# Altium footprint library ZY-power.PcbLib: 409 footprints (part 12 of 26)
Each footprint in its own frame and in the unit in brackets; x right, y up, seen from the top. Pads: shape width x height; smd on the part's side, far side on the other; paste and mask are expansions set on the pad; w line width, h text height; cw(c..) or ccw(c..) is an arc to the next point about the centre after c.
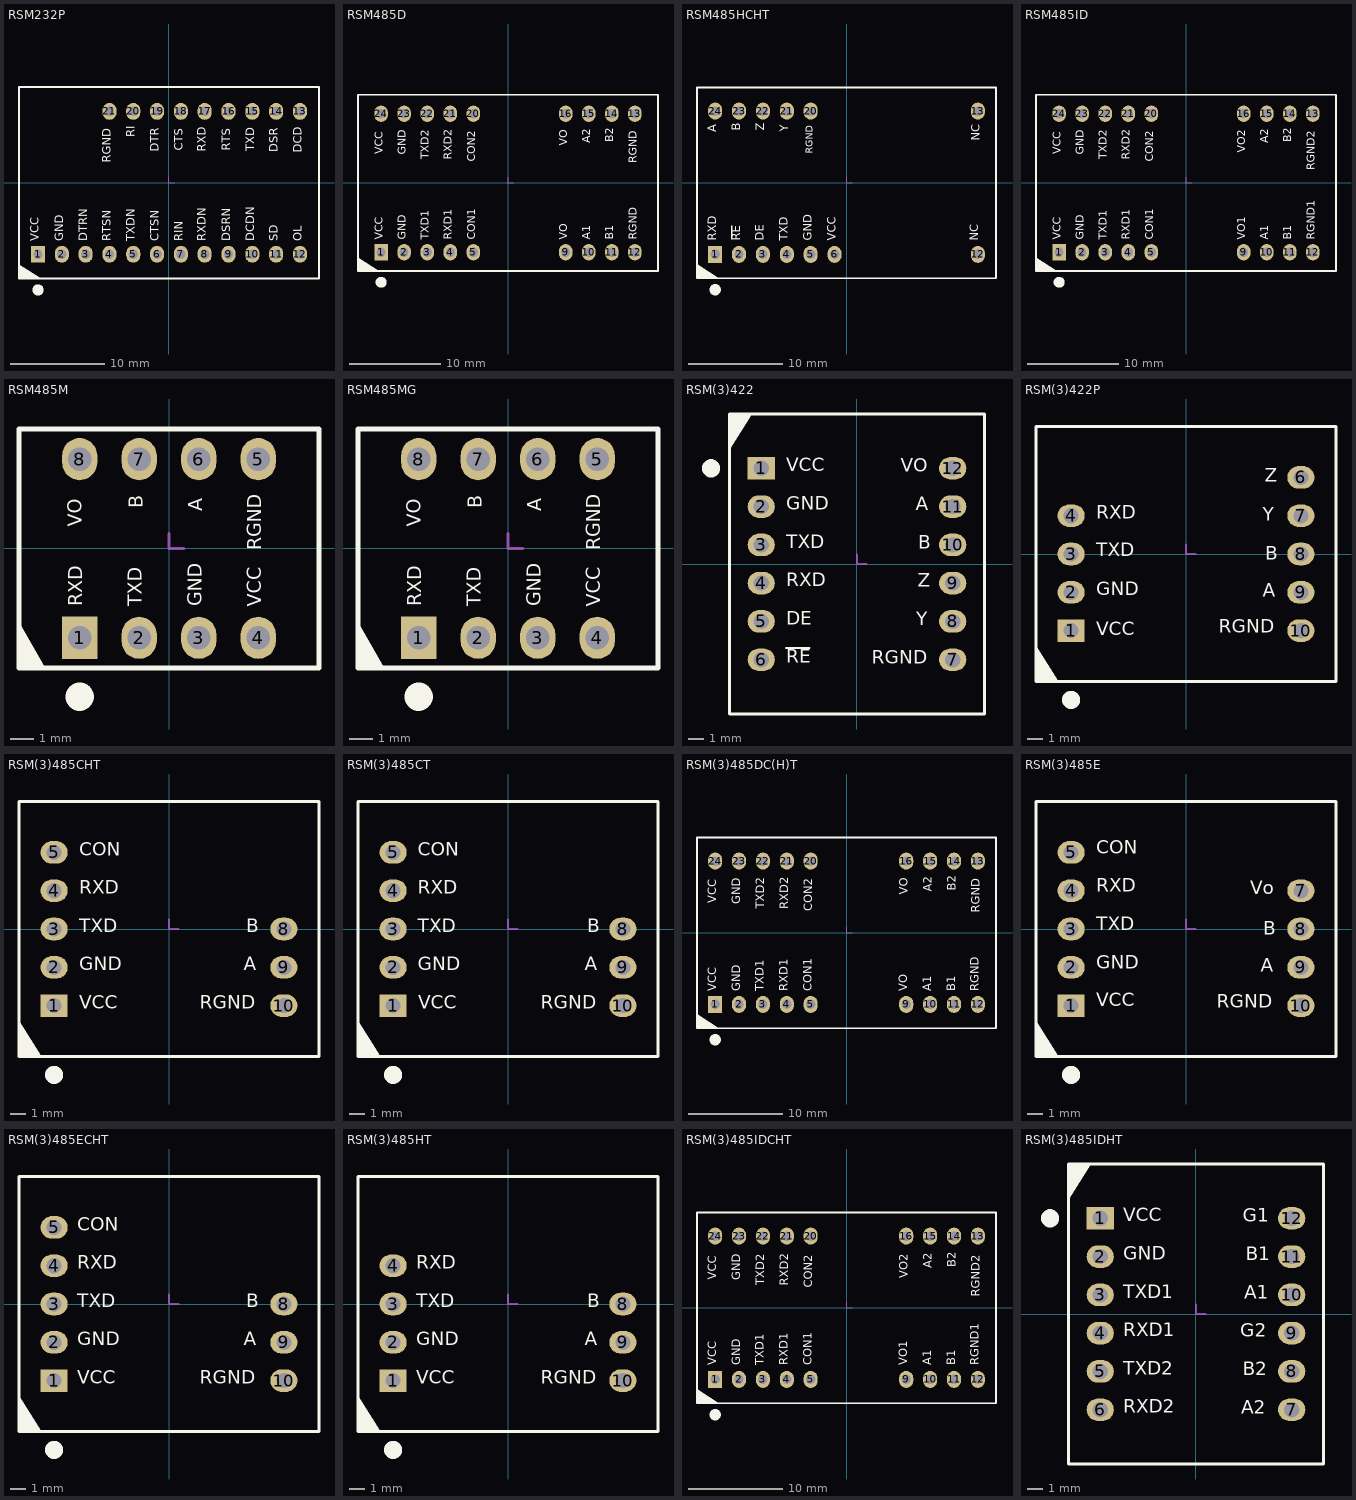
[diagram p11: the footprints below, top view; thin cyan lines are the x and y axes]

## RSM232P [mm]
height 10.5
pads (21):
  rect 1.5x1.8 hole 1: 1(-13.97,-7.62)
  oval 1.5x1.8 hole 1: 2(-11.43,-7.62) 3(-8.89,-7.62) 4(-6.35,-7.62) 5(-3.81,-7.62) 6(-1.27,-7.62) 7(1.27,-7.62) 8(3.81,-7.62) 9(6.35,-7.62) 10(8.89,-7.62) 11(11.43,-7.62) 12(13.97,-7.62) 13(13.97,7.62) 14(11.43,7.62) 15(8.89,7.62) 16(6.35,7.62) 17(3.81,7.62) 18(1.27,7.62) 19(-1.27,7.62) 20(-3.81,7.62) 21(-6.35,7.62)
Top Overlay:
  circle w1: c-13.97,-11.425 r0.1
  region: -13.67,-10.2 -16,-10.2 -16,-8.74
  lines w0.2: -16,-10.2 -16,10.2 16,10.2 16,-10.2 -16,-10.2
  text "RGND" at -5.893,2.159 h1.52
  text "RI" at -3.353,4.856 h1.52
  text "DTR" at -0.787,3.314 h1.52
  text "CTS" at 1.778,3.404 h1.52
  text "RXD" at 4.267,3.293 h1.52
  text "RTS" at 6.833,3.443 h1.52
  text "TXD" at 9.414,3.37 h1.52
  text "DSR" at 11.938,3.236 h1.52
  text "DCD" at 14.478,3.217 h1.52
  text "OL" at 14.478,-6.224 h1.52
  text "SD" at 11.938,-6.224 h1.52
  text "DCDN" at 9.398,-6.224 h1.52
  text "DSRN" at 6.833,-6.224 h1.52
  text "RXDN" at 4.267,-6.224 h1.52
  text "RIN" at 1.762,-6.224 h1.52
  text "CTSN" at -0.787,-6.224 h1.52
  text "TXDN" at -3.353,-6.224 h1.52
  text "RTSN" at -5.893,-6.224 h1.52
  text "DTRN" at -8.407,-6.224 h1.52
  text "GND" at -10.947,-6.224 h1.52
  text "VCC" at -13.564,-6.223 h1.52
Mechanical 15:
  lines w0.127: 0,0.635 0,0 0.635,0
3D body "zhen01.stp": height 6.09, standoff -4.41, extent 6.1,7.37 6.6,7.87
3D body "zhen01.stp": height 6.09, standoff -4.41, extent 8.64,7.37 9.14,7.87
3D body "zhen01.stp": height 6.09, standoff -4.41, extent 11.18,7.37 11.68,7.87
3D body "zhen01.stp": height 6.09, standoff -4.41, extent 13.72,7.37 14.22,7.87
3D body "zhen01.stp": height 6.09, standoff -4.41, extent -6.6,7.37 -6.1,7.87
3D body "zhen01.stp": height 6.09, standoff -4.41, extent -4.06,7.37 -3.56,7.87
3D body "zhen01.stp": height 6.09, standoff -4.41, extent -1.52,7.37 -1.02,7.87
3D body "zhen01.stp": height 6.09, standoff -4.41, extent 1.02,7.37 1.52,7.87
3D body "zhen01.stp": height 6.09, standoff -4.41, extent 3.56,7.37 4.06,7.87
3D body "zhen01.stp": height 6.09, standoff -4.41, extent 11.18,-7.87 11.68,-7.37
3D body "zhen01.stp": height 6.09, standoff -4.41, extent 13.72,-7.87 14.22,-7.37
3D body "zhen01.stp": height 6.09, standoff -4.41, extent -1.52,-7.87 -1.02,-7.37
3D body "zhen01.stp": height 6.09, standoff -4.41, extent 1.02,-7.87 1.52,-7.37
3D body "zhen01.stp": height 6.09, standoff -4.41, extent 3.56,-7.87 4.06,-7.37
3D body "zhen01.stp": height 6.09, standoff -4.41, extent 6.1,-7.87 6.6,-7.37
3D body "zhen01.stp": height 6.09, standoff -4.41, extent 8.64,-7.87 9.14,-7.37
3D body "zhen01.stp": height 6.09, standoff -4.41, extent -4.06,-7.87 -3.56,-7.37
3D body "zhen01.stp": height 6.09, standoff -4.41, extent -6.6,-7.87 -6.1,-7.37
3D body "zhen01.stp": height 6.09, standoff -4.41, extent -9.14,-7.87 -8.64,-7.37
3D body "zhen01.stp": height 6.09, standoff -4.41, extent -11.68,-7.87 -11.18,-7.37
3D body "zhen01.stp": height 6.09, standoff -4.41, extent -14.22,-7.87 -13.72,-7.37
3D body: height 11, standoff 0, extent -16,-10.2 16,10.2

## RSM485D [mm]
height 9.144
pads (18):
  rect 1.5x1.8 hole 1: 1(-13.97,-7.62)
  oval 1.5x1.8 hole 1: 2(-11.43,-7.62) 3(-8.89,-7.62) 4(-6.35,-7.62) 5(-3.81,-7.62) 9(6.35,-7.62) 10(8.89,-7.62) 11(11.43,-7.62) 12(13.97,-7.62) 13(13.97,7.62) 14(11.43,7.62) 15(8.89,7.62) 16(6.35,7.62) 20(-3.81,7.62) 21(-6.35,7.62) 22(-8.89,7.62) 23(-11.43,7.62) 24(-13.97,7.62)
Top Overlay:
  circle w1: c-13.97,-10.928 r0.1
  region: -14.18,-9.703 -16.51,-9.703 -16.51,-8.243
  lines w0.2: -16.51,-9.703 16.51,-9.703 16.51,9.703 -16.51,9.703 -16.51,-9.703
  text "TXD1" at -8.382,-6.224 h1.52
  text "RXD1" at -5.842,-6.224 h1.52
  text "GND" at -10.922,-6.224 h1.52
  text "CON1" at -3.302,-6.224 h1.52
  text "VCC" at -13.462,-6.223 h1.52
  text "VCC" at -13.462,3.172 h1.52
  text "CON2" at -3.302,2.345 h1.52
  text "GND" at -10.922,3.108 h1.52
  text "RXD2" at -5.842,2.533 h1.52
  text "TXD2" at -8.382,2.611 h1.52
  text "B2" at 11.938,4.493 h1.52
  text "A2" at 9.398,4.392 h1.52
  text "RGND" at 14.478,2.159 h1.52
  text "B1" at 11.938,-6.224 h1.52
  text "A1" at 9.398,-6.224 h1.52
  text "RGND" at 14.478,-6.224 h1.52
  text "VO" at 6.858,-6.223 h1.52
  text "VO" at 6.858,4.088 h1.52
Mechanical 15:
  lines w0.127: 0,0.635 0,0 0.635,0

## RSM485HCHT [mm]
height 6.5
pads (13):
  rect 1.5x1.8 hole 1: 1(-13.97,-7.62)
  oval 1.5x1.8 hole 1: 2(-11.43,-7.62) 3(-8.89,-7.62) 4(-6.35,-7.62) 5(-3.81,-7.62) 6(-1.27,-7.62) 12(13.97,-7.62) 13(13.97,7.62) 20(-3.81,7.62) 21(-6.35,7.62) 22(-8.89,7.62) 23(-11.43,7.62) 24(-13.97,7.62)
Top Overlay:
  circle w1: c-13.97,-11.375 r0.1
  region: -13.57,-10.15 -15.9,-10.15 -15.9,-8.69
  lines w0.152: -12.22,-6.02 -12.22,-4.589
  lines w0.2: -15.9,-10.15 15.9,-10.15 15.9,10.15 -15.9,10.15 -15.9,-10.15
  text "NC" at 14.351,-6.147 h1.52
  text "RXD" at -13.538,-6.147 h1.52
  text "RE" at -11.001,-6.147 h1.52
  text "DE" at -8.464,-6.147 h1.52
  text "TXD" at -5.927,-6.147 h1.52
  text "GND" at -3.389,-6.147 h1.52
  text "NC" at 14.478,4.483 h1.52
  text "A" at -13.513,5.382 h1.52
  text "B" at -10.968,5.556 h1.52
  text "Z" at -8.424,5.522 h1.52
  text "RGND" at -3.334,3.097 h1.27
  text "Y" at -5.879,5.4 h1.52
  text "VCC" at -0.852,-6.147 h1.52
Mechanical 15:
  lines w0.127: 0,0.635 0,0 0.635,0

## RSM485ID [mm]
height 9.144
pads (18):
  rect 1.5x1.8 hole 1: 1(-13.97,-7.62)
  oval 1.5x1.8 hole 1: 2(-11.43,-7.62) 3(-8.89,-7.62) 4(-6.35,-7.62) 5(-3.81,-7.62) 9(6.35,-7.62) 10(8.89,-7.62) 11(11.43,-7.62) 12(13.97,-7.62) 13(13.97,7.62) 14(11.43,7.62) 15(8.89,7.62) 16(6.35,7.62) 20(-3.81,7.62) 21(-6.35,7.62) 22(-8.89,7.62) 23(-11.43,7.62) 24(-13.97,7.62)
Top Overlay:
  circle w1: c-13.97,-10.928 r0.1
  region: -14.18,-9.703 -16.51,-9.703 -16.51,-8.243
  lines w0.2: -16.51,-9.703 16.51,-9.703 16.51,9.703 -16.51,9.703 -16.51,-9.703
  text "TXD1" at -8.382,-6.224 h1.52
  text "RXD1" at -5.842,-6.224 h1.52
  text "GND" at -10.922,-6.224 h1.52
  text "CON1" at -3.302,-6.224 h1.52
  text "VCC" at -13.462,-6.223 h1.52
  text "VCC" at -13.462,3.17 h1.52
  text "CON2" at -3.302,2.342 h1.52
  text "GND" at -10.922,3.106 h1.52
  text "RXD2" at -5.842,2.531 h1.52
  text "TXD2" at -8.382,2.608 h1.52
  text "B2" at 11.938,4.491 h1.52
  text "A2" at 9.398,4.39 h1.52
  text "RGND2" at 14.478,1.397 h1.52
  text "B1" at 11.938,-6.224 h1.52
  text "A1" at 9.398,-6.224 h1.52
  text "RGND1" at 14.478,-6.224 h1.52
  text "VO1" at 6.858,-6.223 h1.52
  text "VO2" at 6.858,3.338 h1.52
Mechanical 15:
  lines w0.127: 0,0.635 0,0 0.635,0

## RSM485M [mm]
height 7.7
pads (8):
  rect 1.5x1.8 hole 1: 1(-3.81,-3.81)
  oval 1.5x1.8 hole 1: 2(-1.27,-3.81) 3(1.27,-3.81) 4(3.81,-3.81) 5(3.81,3.81) 6(1.27,3.81) 7(-1.27,3.81) 8(-3.81,3.81)
Top Overlay:
  circle w1: c-3.81,-6.325 r0.1
  region: -5.284,-5.1 -6.4,-3.161 -6.4,-5.1
  lines w0.2: -6.4,-5.1 -6.4,5.1 6.4,5.1 6.4,-5.1 -6.4,-5.1
  text "RGND" at 4.14,-0.072 h1.02
  text "A" at 1.64,1.595 h1.02
  text "B" at -0.914,1.711 h1.02
  text "VO" at -3.505,0.935 h1.02
  text "VCC" at 4.14,-2.485 h1.02
  text "GND" at 1.6,-2.459 h1.02
  text "TXD" at -0.94,-2.459 h1.02
  text "RXD" at -3.491,-2.459 h1.02
Mechanical 15:
  lines w0.127: 0,0.635 0,0 0.635,0
3D body "zhen01.stp": height 6.09, standoff -4.41, extent -4.06,3.56 -3.56,4.06
3D body "zhen01.stp": height 6.09, standoff -4.41, extent -1.52,3.56 -1.02,4.06
3D body "zhen01.stp": height 6.09, standoff -4.41, extent 1.02,3.56 1.52,4.06
3D body "zhen01.stp": height 6.09, standoff -4.41, extent 3.56,3.56 4.06,4.06
3D body "zhen01.stp": height 6.09, standoff -4.41, extent 3.56,-4.06 4.06,-3.56
3D body "zhen01.stp": height 6.09, standoff -4.41, extent 1.02,-4.06 1.52,-3.56
3D body "zhen01.stp": height 6.09, standoff -4.41, extent -1.52,-4.06 -1.02,-3.56
3D body "zhen01.stp": height 6.09, standoff -4.41, extent -4.06,-4.06 -3.56,-3.56
3D body: height 7.7, standoff 0, extent -6.4,-5.1 6.4,5.1

## RSM485MG [mm]
height 7.7
pads (8):
  rect 1.5x1.8 hole 1: 1(-3.81,-3.81)
  oval 1.5x1.8 hole 1: 2(-1.27,-3.81) 3(1.27,-3.81) 4(3.81,-3.81) 5(3.81,3.81) 6(1.27,3.81) 7(-1.27,3.81) 8(-3.81,3.81)
Top Overlay:
  circle w1: c-3.81,-6.325 r0.1
  region: -5.284,-5.1 -6.4,-3.161 -6.4,-5.1
  lines w0.2: -6.4,-5.1 -6.4,5.1 6.4,5.1 6.4,-5.1 -6.4,-5.1
  text "RGND" at 4.14,-0.072 h1.02
  text "A" at 1.64,1.595 h1.02
  text "B" at -0.914,1.711 h1.02
  text "VO" at -3.505,0.935 h1.02
  text "VCC" at 4.14,-2.485 h1.02
  text "GND" at 1.6,-2.459 h1.02
  text "TXD" at -0.94,-2.459 h1.02
  text "RXD" at -3.491,-2.459 h1.02
Mechanical 15:
  lines w0.127: 0,0.635 0,0 0.635,0
3D body: height 7.7, standoff 0, extent -6.4,-5.1 6.4,5.1
3D body "zhen01.stp": height 6.09, standoff -4.41, extent -4.06,-4.06 -3.56,-3.56
3D body "zhen01.stp": height 6.09, standoff -4.41, extent -1.52,-4.06 -1.02,-3.56
3D body "zhen01.stp": height 6.09, standoff -4.41, extent 1.02,-4.06 1.52,-3.56
3D body "zhen01.stp": height 6.09, standoff -4.41, extent 3.56,-4.06 4.06,-3.56
3D body "zhen01.stp": height 6.09, standoff -4.41, extent 3.56,3.56 4.06,4.06
3D body "zhen01.stp": height 6.09, standoff -4.41, extent 1.02,3.56 1.52,4.06
3D body "zhen01.stp": height 6.09, standoff -4.41, extent -1.52,3.56 -1.02,4.06
3D body "zhen01.stp": height 6.09, standoff -4.41, extent -4.06,3.56 -3.56,4.06

## RSM(3)422 [mm]
height 7.05
pads (12):
  rect 1.8x1.5 hole 1: 1(-6.35,6.35)
  oval 1.8x1.5 hole 1: 2(-6.35,3.81) 3(-6.35,1.27) 4(-6.35,-1.27) 5(-6.35,-3.81) 6(-6.35,-6.35) 7(6.35,-6.35) 8(6.35,-3.81) 9(6.35,-1.27) 10(6.35,1.27) 11(6.35,3.81) 12(6.35,6.35)
Top Overlay:
  circle w1: c-9.675,6.35 r0.1
  region: -8.45,7.62 -8.45,9.95 -6.99,9.95
  lines w0.152: -4.694,-5.575 -3.144,-5.575
  lines w0.2: -8.45,-9.95 -8.45,9.95 8.45,9.95 8.45,-9.95 -8.45,-9.95
  text "DE" at -4.7,-4.318 h1.52
  text "RE" at -4.7,-6.858 h1.52
  text "RGND" at 0.983,-6.909 h1.52
  text "Y" at 3.92,-4.364 h1.52
  text "RXD" at -4.7,-1.778 h1.52
  text "TXD" at -4.7,0.762 h1.52
  text "GND" at -4.7,3.302 h1.52
  text "VCC" at -4.699,5.842 h1.52
  text "A" at 3.903,3.272 h1.52
  text "B" at 4.076,0.726 h1.52
  text "Z" at 4.042,-1.819 h1.52
  text "VO" at 2.911,5.817 h1.52
Mechanical 15:
  lines w0.127: 0,0.635 0,0 0.635,0

## RSM(3)422P [mm]
height 7.05
pads (9):
  rect 1.8x1.5 hole 1: 1(-7.62,-5.08)
  oval 1.8x1.5 hole 1: 2(-7.62,-2.54) 3(-7.62,0) 4(-7.62,2.54) 6(7.62,5.08) 7(7.62,2.54) 8(7.62,0) 9(7.62,-2.54) 10(7.62,-5.08)
Top Overlay:
  circle w1: c-7.62,-9.675 r0.1
  region: -9.95,-6.12 -9.95,-8.45 -8.49,-8.45
  lines w0.2: -9.95,-8.45 -9.95,8.45 9.95,8.45 9.95,-8.45 -9.95,-8.45
  text "RGND" at 2.159,-5.537 h1.52
  text "A" at 5.079,-3.124 h1.52
  text "B" at 5.253,-0.686 h1.52
  text "Y" at 5.097,1.905 h1.52
  text "Z" at 5.218,4.496 h1.52
  text "RXD" at -5.969,2.032 h1.52
  text "TXD" at -5.969,-0.457 h1.52
  text "GND" at -5.969,-3.023 h1.52
  text "VCC" at -5.969,-5.69 h1.52
Mechanical 15:
  lines w0.127: 0,0.635 0,0 0.635,0

## RSM(3)485CHT [mm] "嵌入式隔离RS-485收发器"
height 7
pads (8):
  rect 1.8x1.5 hole 1: 1(-7.62,-5.08)
  oval 1.8x1.5 hole 1: 2(-7.62,-2.54) 3(-7.62,0) 4(-7.62,2.54) 5(-7.62,5.08) 8(7.62,0) 9(7.62,-2.54) 10(7.62,-5.08)
Top Overlay:
  circle w1: c-7.62,-9.675 r0.1
  region: -9.95,-6.12 -9.95,-8.45 -8.49,-8.45
  lines w0.2: -9.95,-8.45 -9.95,8.45 9.95,8.45 9.95,-8.45 -9.95,-8.45
  text "VCC" at -5.969,-5.588 h1.52
  text "CON" at -5.969,4.572 h1.52
  text "GND" at -5.969,-3.048 h1.52
  text "RXD" at -5.969,2.032 h1.52
  text "TXD" at -5.969,-0.508 h1.52
  text "RGND" at 2.032,-5.588 h1.52
  text "B" at 5.126,-0.508 h1.52
  text "A" at 4.952,-3.048 h1.52
Mechanical 15:
  lines w0.127: 0,0.635 0,0 0.635,0

## RSM(3)485CT [mm] "嵌入式隔离RS-485收发器"
height 7
pads (8):
  rect 1.8x1.5 hole 1: 1(-7.62,-5.08)
  oval 1.8x1.5 hole 1: 2(-7.62,-2.54) 3(-7.62,0) 4(-7.62,2.54) 5(-7.62,5.08) 8(7.62,0) 9(7.62,-2.54) 10(7.62,-5.08)
Top Overlay:
  circle w1: c-7.62,-9.675 r0.1
  region: -9.95,-6.12 -9.95,-8.45 -8.49,-8.45
  lines w0.2: -9.95,-8.45 9.95,-8.45 9.95,8.45 -9.95,8.45 -9.95,-8.45
  text "A" at 5.079,-3.048 h1.52
  text "B" at 5.253,-0.508 h1.52
  text "RGND" at 2.159,-5.588 h1.52
  text "TXD" at -5.97,-0.508 h1.52
  text "RXD" at -5.97,2.032 h1.52
  text "GND" at -5.97,-3.048 h1.52
  text "CON" at -5.97,4.572 h1.52
  text "VCC" at -5.969,-5.588 h1.52
Mechanical 15:
  lines w0.127: 0,0.635 0,0 0.635,0

## RSM(3)485DC(H)T [mm]
height 9.5
pads (18):
  rect 1.5x1.8 hole 1: 1(-13.97,-7.62)
  oval 1.5x1.8 hole 1: 2(-11.43,-7.62) 3(-8.89,-7.62) 4(-6.35,-7.62) 5(-3.81,-7.62) 9(6.35,-7.62) 10(8.89,-7.62) 11(11.43,-7.62) 12(13.97,-7.62) 13(13.97,7.62) 14(11.43,7.62) 15(8.89,7.62) 16(6.35,7.62) 20(-3.81,7.62) 21(-6.35,7.62) 22(-8.89,7.62) 23(-11.43,7.62) 24(-13.97,7.62)
Top Overlay:
  circle w1: c-13.97,-11.375 r0.1
  region: -13.57,-10.15 -15.9,-10.15 -15.9,-8.69
  lines w0.2: -15.9,-10.15 15.9,-10.15 15.9,10.15 -15.9,10.15 -15.9,-10.15
  text "VCC" at -13.538,-6.223 h1.52
  text "GND" at -10.998,-6.224 h1.52
  text "TXD1" at -8.458,-6.224 h1.52
  text "RXD1" at -5.918,-6.224 h1.52
  text "CON1" at -3.378,-6.224 h1.52
  text "VO" at 6.782,-6.223 h1.52
  text "A1" at 9.322,-6.224 h1.52
  text "B1" at 11.862,-6.224 h1.52
  text "RGND" at 14.402,-6.224 h1.52
  text "RGND" at 14.478,2.108 h1.52
  text "B2" at 11.931,4.443 h1.52
  text "A2" at 9.384,4.342 h1.52
  text "VO" at 6.837,4.037 h1.52
  text "VCC" at -13.538,3.122 h1.52
  text "GND" at -10.991,3.058 h1.52
  text "TXD2" at -8.444,2.56 h1.52
  text "CON2" at -3.35,2.294 h1.52
  text "RXD2" at -5.897,2.483 h1.52
Mechanical 15:
  lines w0.127: 0,0.635 0,0 0.635,0

## RSM(3)485E [mm]
height 7.05
pads (9):
  rect 1.8x1.5 hole 1: 1(-7.62,-5.08)
  oval 1.8x1.5 hole 1: 2(-7.62,-2.54) 3(-7.62,0) 4(-7.62,2.54) 5(-7.62,5.08) 7(7.62,2.54) 8(7.62,0) 9(7.62,-2.54) 10(7.62,-5.08)
Top Overlay:
  circle w1: c-7.62,-9.675 r0.1
  region: -9.95,-6.12 -9.95,-8.45 -8.49,-8.45
  lines w0.2: -9.95,-8.45 9.95,-8.45 9.95,8.45 -9.95,8.45 -9.95,-8.45
  text "VCC" at -5.969,-5.436 h1.52
  text "GND" at -5.969,-2.921 h1.52
  text "TXD" at -5.969,-0.381 h1.52
  text "RXD" at -5.969,2.159 h1.52
  text "CON" at -5.969,4.699 h1.52
  text "Vo" at 4.252,2.007 h1.52
  text "B" at 5.126,-0.686 h1.52
  text "A" at 4.952,-3.124 h1.52
  text "RGND" at 2.032,-5.537 h1.52
Mechanical 15:
  lines w0.127: 0,0.635 0,0 0.635,0

## RSM(3)485ECHT [mm]
height 7.05
pads (8):
  rect 1.8x1.5 hole 1: 1(-7.62,-5.08)
  oval 1.8x1.5 hole 1: 2(-7.62,-2.54) 3(-7.62,0) 4(-7.62,2.54) 5(-7.62,5.08) 8(7.62,0) 9(7.62,-2.54) 10(7.62,-5.08)
Top Overlay:
  circle w1: c-7.62,-9.675 r0.1
  region: -9.95,-6.12 -9.95,-8.45 -8.49,-8.45
  lines w0.2: -9.95,-8.45 -9.95,8.45 9.95,8.45 9.95,-8.45 -9.95,-8.45
  text "VCC" at -6.096,-5.588 h1.52
  text "CON" at -6.097,4.572 h1.52
  text "GND" at -6.097,-3.048 h1.52
  text "RXD" at -6.097,2.032 h1.52
  text "TXD" at -6.097,-0.508 h1.52
  text "RGND" at 2.032,-5.588 h1.52
  text "B" at 5.126,-0.508 h1.52
  text "A" at 4.952,-3.048 h1.52
Mechanical 15:
  lines w0.127: 0,0.635 0,0 0.635,0
3D body: height 7.1, standoff 0, extent -9.95,-8.45 9.95,8.45
3D body "zhen01.stp": height 6.09, standoff -4.41, extent 7.37,-5.33 7.87,-4.83
3D body "zhen01.stp": height 6.09, standoff -4.41, extent 7.37,-2.79 7.87,-2.29
3D body "zhen01.stp": height 6.09, standoff -4.41, extent 7.37,-0.25 7.87,0.25
3D body "zhen01.stp": height 6.09, standoff -4.41, extent -7.87,-5.33 -7.37,-4.83
3D body "zhen01.stp": height 6.09, standoff -4.41, extent -7.87,-2.79 -7.37,-2.29
3D body "zhen01.stp": height 6.09, standoff -4.41, extent -7.87,-0.25 -7.37,0.25
3D body "zhen01.stp": height 6.09, standoff -4.41, extent -7.87,2.29 -7.37,2.79
3D body "zhen01.stp": height 6.09, standoff -4.41, extent -7.87,4.83 -7.37,5.33

## RSM(3)485HT [mm]
height 7.05
pads (7):
  rect 1.8x1.5 hole 1: 1(-7.62,-5.08)
  oval 1.8x1.5 hole 1: 2(-7.62,-2.54) 3(-7.62,0) 4(-7.62,2.54) 8(7.62,0) 9(7.62,-2.54) 10(7.62,-5.08)
Top Overlay:
  circle w1: c-7.62,-9.675 r0.1
  region: -9.95,-6.12 -9.95,-8.45 -8.49,-8.45
  lines w0.2: -9.95,-8.45 -9.95,8.45 9.95,8.45 9.95,-8.45 -9.95,-8.45
  text "VCC" at -6.096,-5.588 h1.52
  text "GND" at -6.097,-3.048 h1.52
  text "RXD" at -6.097,2.032 h1.52
  text "TXD" at -6.097,-0.508 h1.52
  text "RGND" at 2.159,-5.588 h1.52
  text "B" at 5.253,-0.508 h1.52
  text "A" at 5.079,-3.048 h1.52
Mechanical 15:
  lines w0.127: 0,0.635 0,0 0.635,0
3D body "zhen01.stp": height 6.09, standoff -4.41, extent -7.87,2.29 -7.37,2.79
3D body "zhen01.stp": height 6.09, standoff -4.41, extent -7.87,-0.25 -7.37,0.25
3D body "zhen01.stp": height 6.09, standoff -4.41, extent -7.87,-2.79 -7.37,-2.29
3D body "zhen01.stp": height 6.09, standoff -4.41, extent -7.87,-5.33 -7.37,-4.83
3D body "zhen01.stp": height 6.09, standoff -4.41, extent 7.37,-0.25 7.87,0.25
3D body "zhen01.stp": height 6.09, standoff -4.41, extent 7.37,-2.79 7.87,-2.29
3D body "zhen01.stp": height 6.09, standoff -4.41, extent 7.37,-5.33 7.87,-4.83
3D body: height 7.3, standoff 0, extent -9.95,-8.45 9.95,8.45

## RSM(3)485IDCHT [mm]
height 6.5
pads (18):
  rect 1.5x1.8 hole 1: 1(-13.97,-7.62)
  oval 1.5x1.8 hole 1: 2(-11.43,-7.62) 3(-8.89,-7.62) 4(-6.35,-7.62) 5(-3.81,-7.62) 9(6.35,-7.62) 10(8.89,-7.62) 11(11.43,-7.62) 12(13.97,-7.62) 13(13.97,7.62) 14(11.43,7.62) 15(8.89,7.62) 16(6.35,7.62) 20(-3.81,7.62) 21(-6.35,7.62) 22(-8.89,7.62) 23(-11.43,7.62) 24(-13.97,7.62)
Top Overlay:
  circle w1: c-13.97,-11.375 r0.1
  region: -13.57,-10.15 -15.9,-10.15 -15.9,-8.69
  lines w0.2: -15.9,-10.15 15.9,-10.15 15.9,10.15 -15.9,10.15 -15.9,-10.15
  text "VCC" at -13.538,-6.096 h1.52
  text "GND" at -10.998,-6.097 h1.52
  text "TXD1" at -8.458,-6.097 h1.52
  text "RXD1" at -5.918,-6.097 h1.52
  text "CON1" at -3.378,-6.097 h1.52
  text "VO1" at 6.782,-6.096 h1.52
  text "A1" at 9.322,-6.097 h1.52
  text "B1" at 11.862,-6.097 h1.52
  text "RGND1" at 14.402,-6.097 h1.52
  text "RGND2" at 14.478,1.194 h1.52
  text "B2" at 11.931,4.287 h1.52
  text "A2" at 9.384,4.186 h1.52
  text "VO2" at 6.837,3.134 h1.52
  text "VCC" at -13.538,2.966 h1.52
  text "GND" at -10.991,2.903 h1.52
  text "TXD2" at -8.444,2.405 h1.52
  text "CON2" at -3.35,2.139 h1.52
  text "RXD2" at -5.897,2.328 h1.52
Mechanical 15:
  lines w0.127: 0,0.635 0,0 0.635,0
3D body "zhen01.stp": height 6.09, standoff -4.41, extent 6.1,7.37 6.6,7.87
3D body "zhen01.stp": height 6.09, standoff -4.41, extent 8.64,7.37 9.14,7.87
3D body "zhen01.stp": height 6.09, standoff -4.41, extent 11.18,7.37 11.68,7.87
3D body "zhen01.stp": height 6.09, standoff -4.41, extent 13.72,7.37 14.22,7.87
3D body "zhen01.stp": height 6.09, standoff -4.41, extent 6.1,-7.87 6.6,-7.37
3D body "zhen01.stp": height 6.09, standoff -4.41, extent 8.64,-7.87 9.14,-7.37
3D body "zhen01.stp": height 6.09, standoff -4.41, extent 11.18,-7.87 11.68,-7.37
3D body "zhen01.stp": height 6.09, standoff -4.41, extent 13.72,-7.87 14.22,-7.37
3D body "zhen01.stp": height 6.09, standoff -4.41, extent -14.22,-7.87 -13.72,-7.37
3D body "zhen01.stp": height 6.09, standoff -4.41, extent -11.68,-7.87 -11.18,-7.37
3D body "zhen01.stp": height 6.09, standoff -4.41, extent -9.14,-7.87 -8.64,-7.37
3D body "zhen01.stp": height 6.09, standoff -4.41, extent -6.6,-7.87 -6.1,-7.37
3D body "zhen01.stp": height 6.09, standoff -4.41, extent -4.06,-7.87 -3.56,-7.37
3D body "zhen01.stp": height 6.09, standoff -4.41, extent -4.06,7.37 -3.56,7.87
3D body "zhen01.stp": height 6.09, standoff -4.41, extent -6.6,7.37 -6.1,7.87
3D body "zhen01.stp": height 6.09, standoff -4.41, extent -9.14,7.37 -8.64,7.87
3D body "zhen01.stp": height 6.09, standoff -4.41, extent -11.68,7.37 -11.18,7.87
3D body "zhen01.stp": height 6.09, standoff -4.41, extent -14.22,7.37 -13.72,7.87
3D body: height 6.5, standoff 0, extent -15.9,-10.15 15.9,10.15

## RSM(3)485IDHT [mm]
height 7.05
pads (12):
  rect 1.8x1.5 hole 1: 1(-6.35,6.35)
  oval 1.8x1.5 hole 1: 2(-6.35,3.81) 3(-6.35,1.27) 4(-6.35,-1.27) 5(-6.35,-3.81) 6(-6.35,-6.35) 7(6.35,-6.35) 8(6.35,-3.81) 9(6.35,-1.27) 10(6.35,1.27) 11(6.35,3.81) 12(6.35,6.35)
Top Overlay:
  circle w1: c-9.675,6.35 r0.1
  region: -8.45,7.62 -8.45,9.95 -6.99,9.95
  lines w0.2: -8.45,-9.95 -8.45,9.95 8.45,9.95 8.45,-9.95 -8.45,-9.95
  text "TXD2" at -4.827,-4.318 h1.52
  text "RXD2" at -4.827,-6.858 h1.52
  text "A2" at 3.014,-6.909 h1.52
  text "B2" at 3.115,-4.364 h1.52
  text "RXD1" at -4.827,-1.778 h1.52
  text "TXD1" at -4.827,0.762 h1.52
  text "GND" at -4.827,3.302 h1.52
  text "VCC" at -4.826,5.842 h1.52
  text "B1" at 3.294,3.272 h1.52
  text "A1" at 3.193,0.726 h1.52
  text "G2" at 2.939,-1.819 h1.52
  text "G1" at 3.117,5.817 h1.52
Mechanical 15:
  lines w0.127: 0,0.635 0,0 0.635,0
